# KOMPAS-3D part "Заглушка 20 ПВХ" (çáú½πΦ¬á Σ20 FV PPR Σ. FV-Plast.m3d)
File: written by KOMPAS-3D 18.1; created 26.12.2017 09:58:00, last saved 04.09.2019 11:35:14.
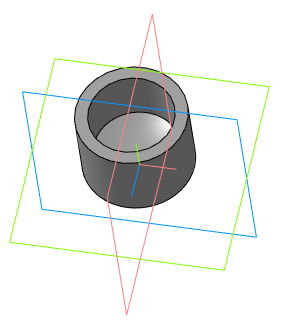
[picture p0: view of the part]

Document properties: Автор: Мирончук; Организация: Мирончук; Полное имя файла: D:\Magna\Магна Ins\Магна ins 10\М10-00.00.000\3Д\Заглушка ф20 FV PPR ф. FV-Plast.m3d

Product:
- Part/product: Заглушка 20 ПВХ
    Масса: 0.0116984
    Раздел спецификации: Прочие изделия
- Part/product: Заглушка @2~20 FV PPR ф. "FV-Plast"  | designation -0
    Масса: 0.0187746
    Раздел спецификации: Прочие изделия

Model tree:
1. Эскиз:1
2. Операция вращения:1
     Угол 1 = 360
